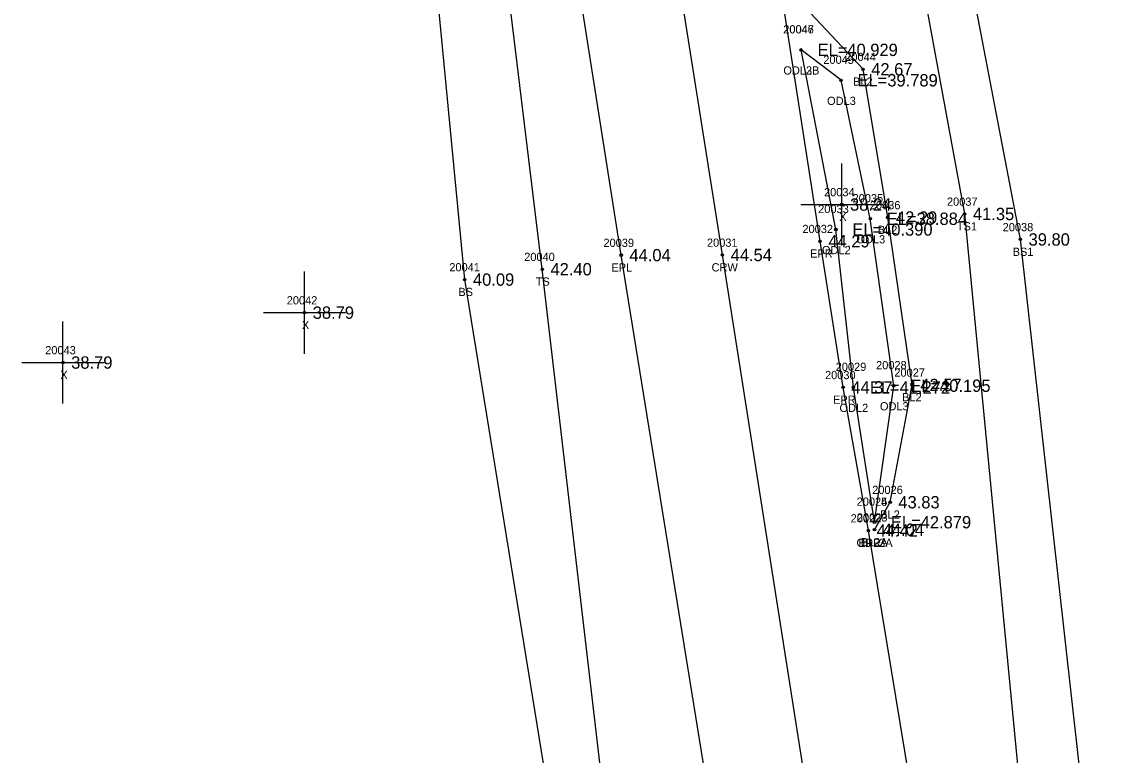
# Model space of a CAD drawing. Extents: x 2619569 to 2620117, y 784503 to 785150.
# Drawn here: x 2619764.9 to 2619897.7, y 784673.4 to 784762.6 of the extents above; entities that cross this region are included whole.
import ezdxf

# ---------------------------------------------------------------- set-up
doc = ezdxf.new("R2010")
doc.units = 0
for name, color, linetype in [('RD_DTM_BkLn1', 7, 'Continuous'), ('RD_DTM_BkLn2', 7, 'Continuous'), ('RD_DTM_BkLn_txCode', 7, 'Continuous'), ('RD_EX_H2O', 7, 'Continuous'), ('RD_EX_H2O_txCode', 7, 'Continuous'), ('RD_EX_Misc', 7, 'Continuous'), ('RD_EX_Misc_txCode', 7, 'Continuous'), ('RD_EX_Road', 7, 'Continuous'), ('RD_EX_Road_txCode', 7, 'Continuous'), ('RD_EX_TX_H2O_ELEV', 7, 'Continuous'), ('RD_EX_TX_Misc_ELEV', 7, 'Continuous'), ('RD_EX_TX_Road_ELEV', 7, 'Continuous'), ('RD_HC_Survey_ELEV', 7, 'Continuous'), ('RD_HC_Survey_txCode', 7, 'Continuous'), ('RD_SMD_Locator', 7, 'Continuous')]:
    doc.layers.add(name, color=color, linetype=linetype)

msp = doc.modelspace()

# ---------------------------------------------------------------- linework, layer by layer
at = {"layer": 'RD_DTM_BkLn1'}
for points in [[(2619883.08, 784523.28), (2619865.99, 784633.65), (2619850.16, 784734.2), (2619838.88, 784805.4)], [(2619868.66, 784700.78), (2619870.56, 784704.13), (2619873.23, 784718.4), (2619870.27, 784738.76), (2619867.26, 784756.79), (2619859.6, 784764.96), (2619858.11, 784765.11)]]:
    msp.add_lwpolyline(points, dxfattribs=at)
at = {"layer": 'RD_DTM_BkLn2'}
for points in [[(2619856.05, 784520.48), (2619839.86, 784632.85), (2619828.25, 784732.47), (2619822.12, 784782.86), (2619822.87, 784803.9), (2619823.81, 784810.14)], [(2619902.71, 784523.57), (2619889.37, 784638.03), (2619879.63, 784739.19), (2619870.48, 784789.08), (2619861.97, 784802.62)], [(2619955.54, 784515.69), (2619919.2, 784522.05), (2619897.31, 784638.51), (2619886.4, 784736.09), (2619876.43, 784788.17), (2619885.46, 784800.96)], [(2619851.2, 784519.25), (2619834.86, 784632.71), (2619818.82, 784731.21), (2619813.99, 784781.54), (2619816.05, 784799.8)]]:
    msp.add_lwpolyline(points, dxfattribs=at)
at = {"layer": 'RD_EX_H2O'}
for points in [[(2619868.65, 784701.7), (2619866.09, 784718.1), (2619863.96, 784737.3), (2619859.73, 784759.15)], [(2619868.65, 784701.7), (2619871.01, 784718.3), (2619868.15, 784738.61), (2619864.59, 784755.45), (2619859.73, 784759.15)]]:
    msp.add_lwpolyline(points, dxfattribs=at)
at = {"layer": 'RD_EX_Misc'}
for p, q in [((2619864.68, 784735.34), (2619864.68, 784745.34)), ((2619859.68, 784740.34), (2619869.68, 784740.34)), ((2619799.33, 784722.19), (2619799.33, 784732.19)), ((2619794.33, 784727.19), (2619804.33, 784727.19)), ((2619769.95, 784716.12), (2619769.95, 784726.12)), ((2619764.95, 784721.12), (2619774.95, 784721.12))]:
    msp.add_line(p, q, dxfattribs=at)
at = {"layer": 'RD_EX_Road'}
for points in [[(2619895.76, 784524.85), (2619878.52, 784636.42), (2619867.91, 784700.67), (2619864.84, 784718.1), (2619862.04, 784735.87), (2619857.49, 784765.12), (2619856.39, 784772.94), (2619851.61, 784802.52), (2619840.88, 784803.5), (2619838.88, 784805.4), (2619833.01, 784808.5), (2619833.86, 784812.8), (2619837.56, 784814.15), (2619849.59, 784815.47), (2619846.37, 784835.55), (2619834.94, 784832.3), (2619822.88, 784832.99)], [(2619871.29, 784521.47), (2619854.2, 784633.24), (2619837.85, 784734.18), (2619826.43, 784806.91), (2619825.69, 784811.44), (2619822.88, 784832.99)]]:
    msp.add_lwpolyline(points, dxfattribs=at)
at = {"layer": 'RD_SMD_Locator'}
for centre in [(2619859.73, 784759.15), (2619859.73, 784759.15), (2619867.26, 784756.79), (2619864.59, 784755.45), (2619864.68, 784740.34), (2619870.27, 784738.76), (2619879.63, 784739.19), (2619868.15, 784738.61), (2619863.96, 784737.3), (2619886.4, 784736.09), (2619862.04, 784735.87), (2619837.85, 784734.18), (2619850.16, 784734.2), (2619828.25, 784732.47), (2619818.82, 784731.21), (2619799.33, 784727.19), (2619769.95, 784721.12), (2619864.84, 784718.1), (2619866.09, 784718.1), (2619871.01, 784718.3), (2619873.23, 784718.4), (2619870.56, 784704.13), (2619868.65, 784701.7), (2619868.65, 784701.7), (2619867.91, 784700.67), (2619868.66, 784700.78)]:
    msp.add_circle(centre, 0.15, dxfattribs=at)

# ---------------------------------------------------------------- texts
at = {"layer": 'RD_DTM_BkLn_txCode'}
for s, p in [('20044', (2619865.1, 784757.79)), ('BL2', (2619866.05, 784754.79)), ('20036', (2619868.09, 784739.76)), ('20037', (2619877.47, 784740.19)), ('BL2', (2619869.06, 784736.76)), ('TS1', (2619878.67, 784737.19)), ('20038', (2619884.25, 784737.09)), ('BS1', (2619885.46, 784734.09)), ('20040', (2619826.05, 784733.47)), ('20041', (2619816.94, 784732.21)), ('TS', (2619827.45, 784730.47)), ('BS', (2619818.04, 784729.21)), ('20027', (2619871.07, 784719.4)), ('BL2', (2619872.02, 784716.4)), ('20026', (2619868.38, 784705.13)), ('BL2', (2619869.35, 784702.13)), ('20023', (2619866.51, 784701.78)), ('BL2A', (2619866.97, 784698.78))]:
    msp.add_text(s, height=1, dxfattribs=at).set_placement(p)
at = {"layer": 'RD_EX_H2O_txCode'}
for s, p in [('20046', (2619857.55, 784761.15)), ('20047', (2619857.57, 784761.15)), ('20045', (2619862.43, 784757.45)), ('ODL2B', (2619857.57, 784756.15)), ('ODL3B', (2619857.57, 784756.15)), ('ODL3', (2619862.89, 784752.45)), ('20035', (2619865.99, 784740.61)), ('20033', (2619861.81, 784739.3)), ('ODL3', (2619866.46, 784735.61)), ('ODL2', (2619862.27, 784734.3)), ('20029', (2619863.94, 784720.1)), ('20028', (2619868.85, 784720.3)), ('ODL3', (2619869.32, 784715.3)), ('ODL2', (2619864.4, 784715.1)), ('20024', (2619866.49, 784703.7)), ('20025', (2619866.49, 784703.7)), ('ODL2A', (2619866.47, 784698.7)), ('ODL3A', (2619866.47, 784698.7))]:
    msp.add_text(s, height=1, dxfattribs=at).set_placement(p)
at = {"layer": 'RD_EX_Misc_txCode'}
for s, p in [('20034', (2619862.52, 784741.34)), ('X', (2619864.37, 784738.34)), ('20042', (2619797.17, 784728.19)), ('X', (2619799.01, 784725.19)), ('20043', (2619767.79, 784722.12)), ('X', (2619769.63, 784719.12))]:
    msp.add_text(s, height=1, dxfattribs=at).set_placement(p)
at = {"layer": 'RD_EX_Road_txCode'}
for s, p in [('20032', (2619859.89, 784736.87)), ('20039', (2619835.69, 784735.18)), ('EPR', (2619860.82, 784733.87)), ('EPL', (2619836.65, 784732.18)), ('20030', (2619862.64, 784719.1)), ('EPR', (2619863.61, 784716.1)), ('20022', (2619865.76, 784701.67)), ('EPR', (2619866.69, 784698.67))]:
    msp.add_text(s, height=1, dxfattribs=at).set_placement(p)
at = {"layer": 'RD_EX_TX_H2O_ELEV'}
for s, p in [('EL=40.929', (2619861.73, 784758.4)), ('EL=40.929', (2619861.73, 784758.4)), ('EL=39.789', (2619866.59, 784754.7)), ('EL=38.884', (2619870.15, 784737.86)), ('EL=40.390', (2619865.96, 784736.55)), ('EL=40.195', (2619873.01, 784717.55)), ('EL=41.272', (2619868.09, 784717.35)), ('EL=42.879', (2619870.65, 784700.95)), ('EL=42.879', (2619870.65, 784700.95))]:
    msp.add_text(s, height=1.5, dxfattribs=at).set_placement(p)
at = {"layer": 'RD_EX_TX_Misc_ELEV'}
for s, p in [('42.67', (2619868.26, 784756.04)), ('38.24', (2619865.68, 784739.59)), ('42.29', (2619871.27, 784738.01)), ('41.35', (2619880.63, 784738.44)), ('39.80', (2619887.4, 784735.34)), ('42.40', (2619829.25, 784731.72)), ('40.09', (2619819.82, 784730.46)), ('38.79', (2619800.33, 784726.44)), ('38.79', (2619770.95, 784720.37)), ('42.57', (2619874.23, 784717.65)), ('43.83', (2619871.56, 784703.38)), ('44.04', (2619869.66, 784700.03))]:
    msp.add_text(s, height=1.5, dxfattribs=at).set_placement(p)
at = {"layer": 'RD_EX_TX_Road_ELEV'}
for s, p in [('44.29', (2619863.04, 784735.12)), ('44.04', (2619838.85, 784733.43)), ('44.37', (2619865.84, 784717.35)), ('44.42', (2619868.91, 784699.92))]:
    msp.add_text(s, height=1.5, dxfattribs=at).set_placement(p)
at = {"layer": 'RD_HC_Survey_ELEV'}
msp.add_text('44.54', height=1.5, dxfattribs=at).set_placement((2619851.16, 784733.45))
at = {"layer": 'RD_HC_Survey_txCode'}
for s, p in [('20031', (2619848.28, 784735.2)), ('CRW', (2619848.84, 784732.2))]:
    msp.add_text(s, height=1, dxfattribs=at).set_placement(p)

doc.saveas('drawing.dxf')
